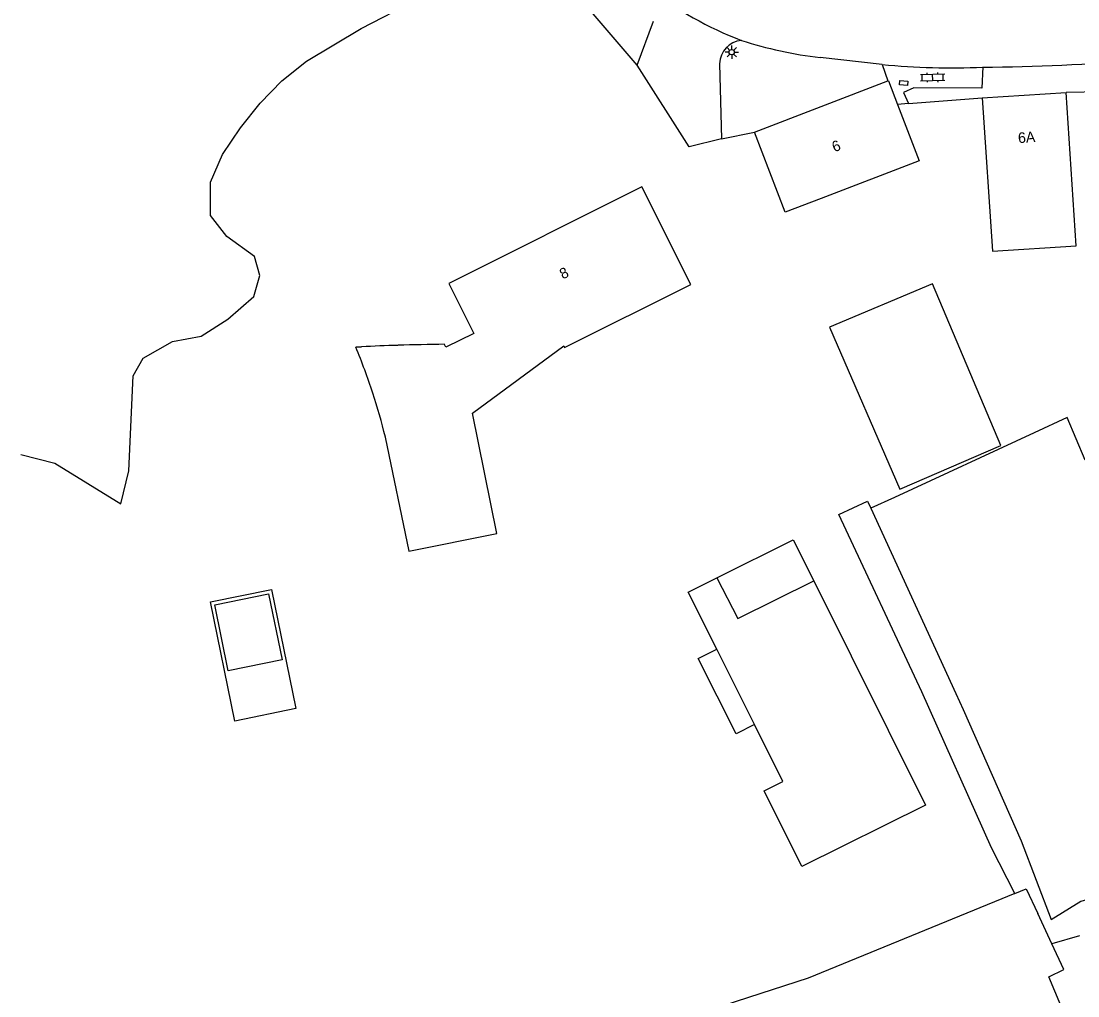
# Model space of a CAD drawing. Extents: x 135999 to 138000, y 396000 to 398501.
# Drawn here: x 136349 to 136449, y 396780.3 to 396872.6 of the extents above; entities that cross this region are included whole.
import ezdxf

# ---------------------------------------------------------------- set-up
doc = ezdxf.new("R2010")
doc.units = 0
for name, color, linetype in [('gg-afsc-draadraster', 7, 'Continuous'), ('gg-afsc-erfafscheiding', 7, 'Continuous'), ('gg-anno-huisnummerreeks BGT', 7, 'Continuous'), ('gg-bbg-bijgebouw', 7, 'Continuous'), ('gg-bbg-gedigitaliseerde bebouwing', 7, 'Continuous'), ('gg-bbg-hoofdgebouw', 7, 'Continuous'), ('gg-bbg-luifel en loopbrug', 7, 'Continuous'), ('gg-bbg-pand overbouw', 7, 'Continuous'), ('gg-knt-bronhoudergrens', 7, 'Continuous'), ('gg-knt-verharding', 7, 'Continuous'), ('gg-knt-verharding nz', 7, 'Continuous'), ('gg-kntw-bovenkant insteek waterloop', 7, 'Continuous'), ('gg-kwrk-keermuur', 7, 'Continuous'), ('gt-grn-groengrens', 7, 'Continuous'), ('gt-grn-vlakafsluiter', 7, 'Continuous'), ('gt-symb-klinker verharding', 7, 'Continuous'), ('gt-symb-kolk center center', 7, 'Continuous'), ('gt-symb-lichtmast', 7, 'Continuous')]:
    doc.layers.add(name, color=color, linetype=linetype)

# ---------------------------------------------------------------- blocks, each defined once
blk = doc.blocks.new('gt0-KOLKCC')
at = {"layer": 'gt-symb-kolk center center'}
blk.add_lwpolyline([(-0.38, 0.2), (0.38, 0.2), (0.38, -0.2), (-0.38, -0.2)], close=True, dxfattribs=at)
blk = doc.blocks.new('gt0-KL1')
at = {"layer": 'gt-symb-klinker verharding'}
for p, q in [((-1.15, 0.3), (1.15, 0.3)), ((-1, -0.3), (-1, 0.3)), ((-0.5, 0.3), (-0.5, 0.45)), ((0, -0.3), (0, 0.3)), ((0.5, 0.3), (0.5, 0.45)), ((1, -0.3), (1, 0.3)), ((-1.15, -0.3), (1.15, -0.3)), ((-0.5, -0.45), (-0.5, -0.3)), ((0.5, -0.45), (0.5, -0.3))]:
    blk.add_line(p, q, dxfattribs=at)
blk = doc.blocks.new('gt0-LMAST')
at = {"layer": 'gt-symb-lichtmast'}
for p, q in [((-0.18, 0.17), (-0.45, 0.44)), ((-0.01, 0.25), (-0.01, 0.62)), ((0.17, 0.17), (0.44, 0.44)), ((-0.26, 0), (-0.63, 0)), ((-0.18, -0.18), (-0.45, -0.45)), ((-0.01, -0.25), (-0.01, -0.63)), ((0.44, -0.45), (0.17, -0.18)), ((0.24, 0), (0.62, 0))]:
    blk.add_line(p, q, dxfattribs=at)
blk.add_circle((-0.01, 0), 0.25, dxfattribs=at)

msp = doc.modelspace()

# ---------------------------------------------------------------- linework, layer by layer
at = {"layer": 'gg-afsc-draadraster'}
for points in [[(136348.94, 396831.55), (136352.13, 396830.73), (136358.39, 396826.87), (136359.16, 396830), (136359.57, 396838.98), (136360.51, 396840.67), (136363.27, 396842.24), (136365.98, 396842.75), (136368.52, 396844.36), (136370.98, 396846.51), (136371.53, 396848.5), (136371.05, 396850.28), (136368.41, 396852.17), (136366.88, 396854.17), (136366.89, 396857.32), (136368, 396859.94), (136369.7, 396862.46), (136371.56, 396864.81), (136373.62, 396866.93), (136375.96, 396868.77), (136381.15, 396871.87), (136386.28, 396874.53)], [(136442.99, 396790), (136423.43, 396781.98), (136412.05, 396778.27), (136432.29, 396726.02), (136446.13, 396687.66)]]:
    msp.add_lwpolyline(points, dxfattribs=at)
at = {"layer": 'gg-afsc-erfafscheiding'}
msp.add_line((136432.94, 396864.77), (136439.92, 396865.31), dxfattribs=at)
at = {"layer": 'gg-bbg-bijgebouw'}
for p, q in [((136439.92, 396865.31), (136447.85, 396865.83)), ((136418.35, 396805.97), (136414.78, 396813.11))]:
    msp.add_line(p, q, dxfattribs=at)
for points in [[(136439.92, 396865.31), (136440.87, 396850.79), (136448.8, 396851.31), (136447.85, 396865.83)], [(136425.45, 396843.59), (136432.1, 396828.25), (136441.67, 396832.4), (136435.2, 396847.7), (136425.45, 396843.59)], [(136414.78, 396813.11), (136412.09, 396818.51), (136414.81, 396819.87)], [(136414.81, 396819.87), (136416.77, 396816.01), (136423.96, 396819.58)], [(136423.96, 396819.58), (136434.54, 396798.34), (136422.85, 396792.54), (136419.27, 396799.72), (136421.03, 396800.59), (136418.35, 396805.97)], [(136372.38, 396818.36), (136373.66, 396812.11), (136368.56, 396811.06), (136367.29, 396817.32), (136372.38, 396818.36)]]:
    msp.add_lwpolyline(points, dxfattribs=at)
at = {"layer": 'gg-bbg-gedigitaliseerde bebouwing'}
for p, q in [((136431.03, 396866.93), (136431.89, 396864.68)), ((136421.27, 396854.48), (136418.36, 396862.07)), ((136424.67, 396855.78), (136421.27, 396854.48))]:
    msp.add_line(p, q, dxfattribs=at)
msp.add_lwpolyline([(136431.89, 396864.68), (136433.94, 396859.34), (136424.67, 396855.78)], dxfattribs=at)
at = {"layer": 'gg-bbg-hoofdgebouw'}
for p, q in [((136418.36, 396862.07), (136430.97, 396866.91)), ((136430.97, 396866.91), (136431.03, 396866.93)), ((136380.63, 396841.73), (136381.16, 396841.75))]:
    msp.add_line(p, q, dxfattribs=at)
msp.add_lwpolyline([(136383.42, 396833.19), (136385.64, 396822.38), (136393.96, 396824.07), (136391.68, 396835.47), (136400.3, 396841.83), (136400.39, 396841.67), (136412.35, 396847.63), (136407.69, 396856.88), (136389.42, 396847.74), (136391.79, 396843), (136389.16, 396841.71), (136389.03, 396841.97)], dxfattribs=at)
for centre, radius, start, end in [((136326.87, 396819.35), 58.22, 18.0133, 22.5945), ((136390.93, 396627.98), 213.99, 91.6897, 92.6162), ((136392.59, 396571.45), 270.55, 90.7532, 91.6878), ((136328.49, 396819.86), 56.53, 13.6448, 18.0352)]:
    msp.add_arc(centre, radius, start, end, dxfattribs=at)
at = {"layer": 'gg-bbg-luifel en loopbrug'}
msp.add_lwpolyline([(136366.88, 396817.6), (136372.66, 396818.77), (136374.95, 396807.51), (136369.17, 396806.31), (136366.88, 396817.6)], dxfattribs=at)
at = {"layer": 'gg-bbg-pand overbouw'}
for points in [[(136414.81, 396819.87), (136422.02, 396823.48), (136423.96, 396819.58)], [(136418.35, 396805.97), (136416.61, 396805.1), (136413.03, 396812.24), (136414.78, 396813.11)]]:
    msp.add_lwpolyline(points, dxfattribs=at)
at = {"layer": 'gg-knt-bronhoudergrens'}
for p, q in [((136444.83, 396833.61), (136431.62, 396827.49)), ((136431.62, 396827.49), (136429.37, 396826.45))]:
    msp.add_line(p, q, dxfattribs=at)
for points in [[(136453.24, 396865.92), (136453.55, 396855.64), (136465.58, 396839.35), (136454.85, 396832.52), (136449.66, 396831.02), (136447.94, 396835.05), (136444.83, 396833.61)], [(136442.99, 396790), (136444.06, 396790.44), (136445.18, 396788.1)]]:
    msp.add_lwpolyline(points, dxfattribs=at)
at = {"layer": 'gg-knt-verharding'}
for p, q in [((136407.26, 396868.39), (136408.79, 396872.57)), ((136430.45, 396868.48), (136424.57, 396869.13)), ((136415.05, 396868.54), (136415.24, 396861.42)), ((136430.45, 396868.48), (136430.97, 396866.91))]:
    msp.add_line(p, q, dxfattribs=at)
for points in [[(136415.24, 396861.42), (136412.17, 396860.68), (136407.26, 396868.39)], [(136439.96, 396868.23), (136439.88, 396866.22), (136433.44, 396866.25), (136432.45, 396865.82), (136432.94, 396864.77)]]:
    msp.add_lwpolyline(points, dxfattribs=at)
for centre, radius, start, end in [((136430.22, 396904.5), 36.21, 232.8202, 248.7907), ((136417.32, 396868.48), 2.27, 95.0588, 178.4791), ((136429.04, 396907.8), 38.93, 252.168, 263.4084), ((136438.2, 397084.39), 216.18, 270.4649, 274.4412), ((136436.95, 396933.31), 65.16, 264.2797, 272.6458)]:
    msp.add_arc(centre, radius, start, end, dxfattribs=at)
at = {"layer": 'gg-knt-verharding nz'}
msp.add_line((136432.94, 396864.77), (136431.89, 396864.68), dxfattribs=at)
at = {"layer": 'gg-kntw-bovenkant insteek waterloop'}
for p, q in [((136429.06, 396827.13), (136429.37, 396826.45)), ((136429.37, 396826.45), (136437.4, 396808.93)), ((136449.12, 396785.99), (136446.5, 396785.23))]:
    msp.add_line(p, q, dxfattribs=at)
for points in [[(136446.45, 396787.53), (136449.25, 396789.27), (136451.28, 396789.79), (136511.6, 396810.32), (136480.93, 396867.69)], [(136442.99, 396790), (136440.79, 396794.31), (136434.21, 396809.07), (136426.33, 396825.88), (136429.06, 396827.13)], [(136437.4, 396808.93), (136438.1, 396807.39), (136443.61, 396794.97), (136446.45, 396787.53)], [(136479.29, 396688.48), (136479.15, 396688.88), (136473.34, 396706.92), (136464.5, 396737.61), (136461.04, 396746.09), (136456.21, 396758.21), (136446.22, 396782.11)]]:
    msp.add_lwpolyline(points, dxfattribs=at)
at = {"layer": 'gg-kwrk-keermuur'}
msp.add_line((136446.5, 396785.23), (136445.18, 396788.1), dxfattribs=at)
msp.add_lwpolyline([(136446.22, 396782.11), (136447.62, 396782.79), (136446.5, 396785.23)], dxfattribs=at)
at = {"layer": 'gt-grn-groengrens'}
msp.add_line((136453.24, 396865.92), (136447.85, 396865.83), dxfattribs=at)
at = {"layer": 'gt-grn-vlakafsluiter'}
for p, q in [((136407.26, 396868.39), (136401.68, 396874.91)), ((136415.24, 396861.42), (136418.36, 396862.07))]:
    msp.add_line(p, q, dxfattribs=at)

# ---------------------------------------------------------------- block references
at = {"layer": 'gt-symb-klinker verharding', "rotation": 0.9166542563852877}
msp.add_blockref('gt0-KL1', (136435.22, 396867.25), dxfattribs=at)
at = {"layer": 'gt-symb-kolk center center', "rotation": -4.877880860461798}
msp.add_blockref('gt0-KOLKCC', (136432.49, 396866.72), dxfattribs=at)
at = {"layer": 'gt-symb-lichtmast'}
msp.add_blockref('gt0-LMAST', (136416.21, 396869.63), dxfattribs=at)

# ---------------------------------------------------------------- texts
at = {"layer": 'gg-anno-huisnummerreeks BGT'}
for s, rotation, p in [('6A', 3.8, (136443.33, 396861.02)), ('6', 21, (136425.92, 396860.15)), ('8', 26.6, (136400.22, 396848.11))]:
    msp.add_text(s, height=1, rotation=rotation, dxfattribs=at).set_placement(p)

doc.saveas('drawing.dxf')
